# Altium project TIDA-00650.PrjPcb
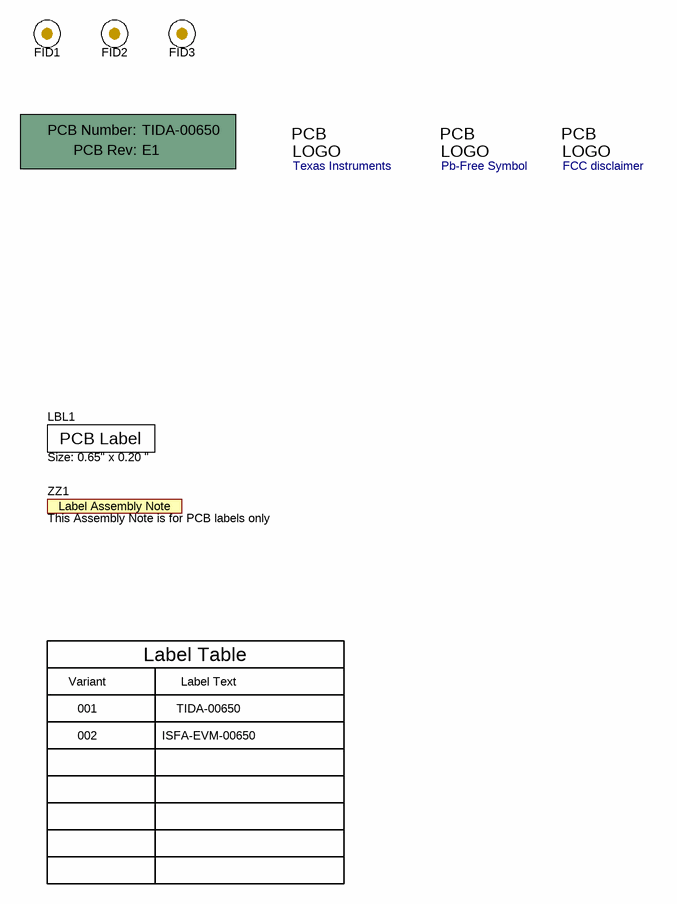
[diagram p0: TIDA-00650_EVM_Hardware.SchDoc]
CopyrightYear: 2015; PCB_Layout: AW; PCB_Rev: E1; PRJ_Customer: Public Release; PRJ_Engineer: AW; PRJ_Number: TIDA-00650; PRJ_Title: Wireless TC Sensor; SCH_Rev: E1; TechSupport: http://www.ti.com/support; TID: TIDA-00650
3 sheets, 54 parts. Net scope: flat (ports and power ports of the same name join across sheets).
Board file: TIDA-00650_EVM.PcbDoc
Sheets:
  TIDA-00650_CoverSheet.SchDoc
  TIDA-00650_EVM_Hardware.SchDoc
  TIDA-00650_ADC.SchDoc

## Sheet TIDA-00650_CoverSheet.SchDoc: Block Diagram
size 431 x 279 mm; Date: Not shown in title block; ApprovedBy: Not shown in title block; CheckedBy: Not shown in title block; Author: Not shown in title block; CompanyName: Not shown in title block; DrawnBy: AW; Engineer: Not shown in title block; Organization: Not shown in title block; Address1: Not shown in title block; Address2: Not shown in title block; Address3: Not shown in title block; Address4: Not shown in title block; DocumentNumber: 1; Revision: Use project parameter SCH_Rev; SheetNumber: 1; SheetTotal: 3; PageSetup: Record=PageOptions¦CenterHorizontal=True¦CenterVertical=True¦PrintScale=1.00¦XCorrection=1.00¦YCorrection=1.00¦PrintKind=0¦BorderSize=5000000¦LeftOffset=0¦BottomOffset=0¦Orientation=2¦PaperLength=1000¦PaperWidth=1000¦Scale=100¦PaperSource=15¦PrintQuality=600¦MediaType=1¦DitherType=10¦PaperKind=Letter¦PrintScaleMode=1

## Sheet TIDA-00650_EVM_Hardware.SchDoc: Hardware
size 431 x 279 mm; Date: Not shown in title block; ApprovedBy: Not shown in title block; CheckedBy: Not shown in title block; Author: Not shown in title block; CompanyName: Not shown in title block; DrawnBy: AW; Engineer: Not shown in title block; Organization: Not shown in title block; Address1: Not shown in title block; Address2: Not shown in title block; Address3: Not shown in title block; Address4: Not shown in title block; DocumentNumber: 1; Revision: Use project parameter SCH_Rev; SheetNumber: 3; SheetTotal: 3; PageSetup: Record=PageOptions¦CenterHorizontal=True¦CenterVertical=True¦PrintScale=1.00¦XCorrection=1.00¦YCorrection=1.00¦PrintKind=0¦BorderSize=5000000¦LeftOffset=0¦BottomOffset=0¦Orientation=2¦PaperLength=1000¦PaperWidth=1000¦Scale=100¦PaperSource=15¦PrintQuality=600¦MediaType=1¦DitherType=10¦PaperKind=Letter¦PrintScaleMode=1

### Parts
!PCB1  Printed Circuit Board  (value not drawn)  (mechanical)
FID1  Fiducial  [Fiducial10-20]  (value not drawn)
FID2  Fiducial  [Fiducial10-20]  (value not drawn)
FID3  Fiducial  [Fiducial10-20]  (value not drawn)
LBL1  Size: 0.65" x 0.20 "  [Label_650x200]
Logo1  Texas Instruments  [TI_Stacked_Overlay_Small]  (no BOM)
Logo2  Pb-Free Symbol  [Pb-Free_Overlay_Small]  (no BOM)
Logo3  FCC disclaimer  [FCC_disclaimer_stacked]  (no BOM)
ZZ1  This Assembly Note is for PCB labels only  [AssemblyNoteLabel]  (no BOM)

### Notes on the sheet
- Label Table
- Variant
- 001
- Label Text
- TIDA-00650
- 002
- ISFA-EVM-00650

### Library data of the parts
!PCB1 = PCB: Manufacturer: Any; PartNumber: TIDA-00650; SymbolCreator: a0412235
FID1-FID3 = Fiducial: Fiducial mark.  There is nothing to buy or mount.; SymbolCreator: codlsc
LBL1 = THT-14-423-10: Thermal Transfer Printable Labels, 0.650" W x 0.200" H - 10,000 per roll; Manufacturer: Brady; SymbolCreator: a0412235; CompType: Label
Logo1 = TI_Logo: Texas Instrument Corporate Signature; SymbolCreator: a0412235
Logo2 = Pb-Free: SymbolCreator: a0412235
Logo3 = FCC_disclaimer: SymbolCreator: codlsc
ZZ1 = AssemblyNoteLabel: SymbolCreator: a0412235

## Sheet TIDA-00650_ADC.SchDoc: Thermocouple ADC circuitry
size 431 x 279 mm; Date: Not shown in title block; ApprovedBy: Not shown in title block; CheckedBy: Not shown in title block; Author: Not shown in title block; CompanyName: Not shown in title block; DrawnBy: AW; Engineer: Not shown in title block; Organization: Not shown in title block; Address1: Not shown in title block; Address2: Not shown in title block; Address3: Not shown in title block; Address4: Not shown in title block; DocumentNumber: 1; Revision: Use project parameter SCH_Rev; SheetNumber: 2; SheetTotal: 3; PageSetup: Record=PageOptions¦CenterHorizontal=True¦CenterVertical=True¦PrintScale=1.00¦XCorrection=1.00¦YCorrection=1.00¦PrintKind=0¦BorderSize=5000000¦LeftOffset=0¦BottomOffset=0¦Orientation=2¦PaperLength=1000¦PaperWidth=1000¦Scale=100¦PaperSource=15¦PrintQuality=600¦MediaType=1¦DitherType=10¦PaperKind=Letter¦PrintScaleMode=1
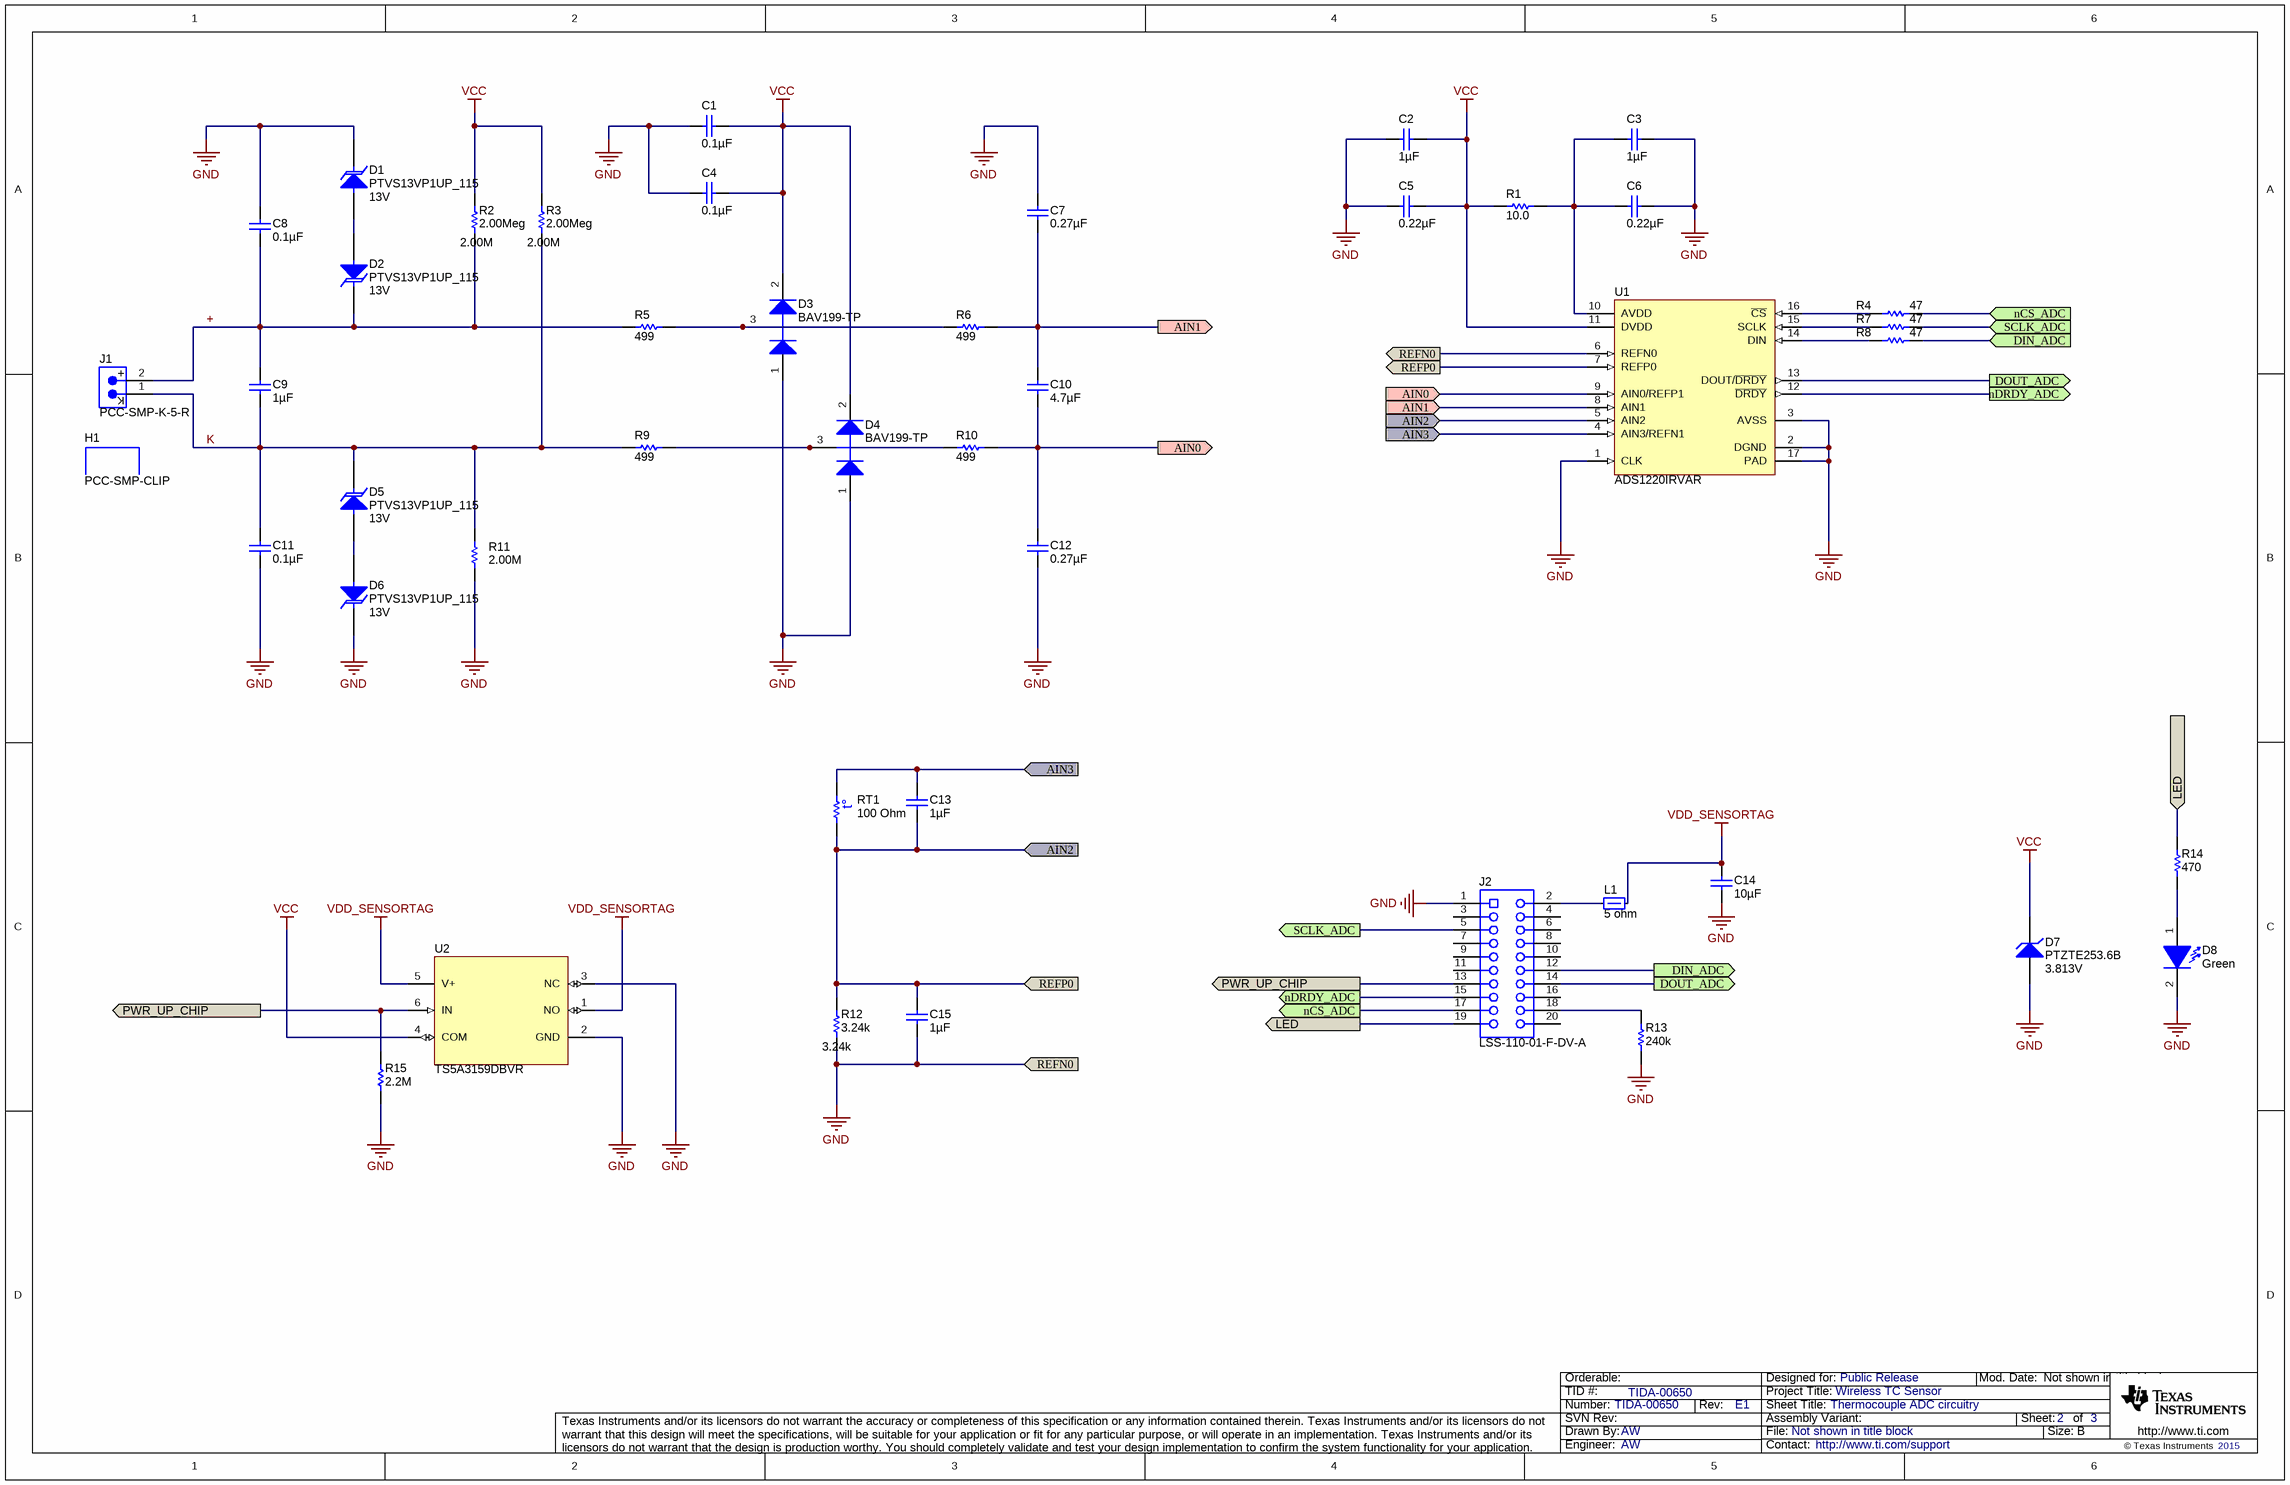
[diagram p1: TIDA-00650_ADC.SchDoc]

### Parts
C1  ValueDisplayed: 0.1µF  [0402]  (hidden comment: C1005X7R1H104K050BB)
C2  ValueDisplayed: 1µF  [0402S]  (hidden comment: GRM155R61A105KE15D)
C3  ValueDisplayed: 1µF  [0402S]  (hidden comment: GRM155R61A105KE15D)
C4  ValueDisplayed: 0.1µF  [0402]  (hidden comment: C1005X7R1H104K050BB)
C5  ValueDisplayed: 0.22µF  [0402S]  (hidden comment: GRM155R60J224KE01D)
C6  ValueDisplayed: 0.22µF  [0402S]  (hidden comment: GRM155R60J224KE01D)
C7  ValueDisplayed: 0.27µF  [0402L]  (hidden comment: GRM155R60J274KE01D)
C8  ValueDisplayed: 0.1µF  [0402]  (hidden comment: C1005X7R1H104K050BB)
C9  ValueDisplayed: 1µF  [0603]  (hidden comment: UMK107AB7105KA-T)
C10  ValueDisplayed: 4.7µF  [0402S]  (hidden comment: C1005X5R1A475K050BC)
C11  ValueDisplayed: 0.1µF  [0402]  (hidden comment: C1005X7R1H104K050BB)
C12  ValueDisplayed: 0.27µF  [0402L]  (hidden comment: GRM155R60J274KE01D)
C13  ValueDisplayed: 1µF  [0402S]  (hidden comment: GRM155R61A105KE15D)
C14  ValueDisplayed: 10µF  [0402S]  (hidden comment: GRM155R61A106ME11)
C15  ValueDisplayed: 1µF  [0402S]  (hidden comment: GRM155R61A105KE15D)
D1  PTVS13VP1UP_115  value 13V  [SOD-128]
D2  PTVS13VP1UP_115  value 13V  [SOD-128]
D3  BAV199-TP  [SOT-23]
D4  BAV199-TP  [SOT-23]
D5  PTVS13VP1UP_115  value 13V  [SOD-128]
D6  PTVS13VP1UP_115  value 13V  [SOD-128]
D7  PTZTE253.6B  value 3.813V  [SMA]
D8  value Green  [LG L29K_GREEN]  (hidden comment: LG L29K-G2J1-24-Z)
H1  PCC-SMP-CLIP  (mechanical)
J1  PCC-SMP-K-5-R  [Omega_PCC-SMP-K]
J2  LSS-110-01-F-DV-A  [Samtec_LSS-110-01-F-DV-A]
L1  value 5 ohm  [0603S]  (hidden comment: BLM18BB050SN1D)
R1  ValueDisplayed: 10.0  [0402S]  (hidden comment: CRCW040210R0FKED)
R2  value 2.00Meg  ValueDisplayed: 2.00M  [0402]  (hidden comment: CRCW04022M00FKED)
R3  value 2.00Meg  ValueDisplayed: 2.00M  [0402]  (hidden comment: CRCW04022M00FKED)
R4  ValueDisplayed: 47  [0402S]  (hidden comment: CRCW040247R0JNED)
R5  ValueDisplayed: 499  [0402]  (hidden comment: CRCW0402499RFKED)
R6  ValueDisplayed: 499  [0402L]  (hidden comment: CRCW0402499RFKED)
R7  ValueDisplayed: 47  [0402S]  (hidden comment: CRCW040247R0JNED)
R8  ValueDisplayed: 47  [0402S]  (hidden comment: CRCW040247R0JNED)
R9  ValueDisplayed: 499  [0402]  (hidden comment: CRCW0402499RFKED)
R10  ValueDisplayed: 499  [0402L]  (hidden comment: CRCW0402499RFKED)
R11  ValueDisplayed: 2.00M  [0402]  (hidden comment: CRCW04022M00FKED)
R12  value 3.24k  [1206L]  (hidden comment: PFC-W1206R-12-3241-B)
R13  ValueDisplayed: 240k  [0402]  (hidden comment: CRCW0402240KFKED)
R14  ValueDisplayed: 470  [0402]  (hidden comment: ERJ-2RKF4700X)
R15  ValueDisplayed: 2.2M  [0402S]  (hidden comment: CRCW04022M20JNED)
RT1  value 100 Ohm  [TO-92_Heraeus]  (hidden comment: 32209210)
U1  ADS1220IRVAR  [RVA0016A]
U2  TS5A3159DBVR  [DBV0006A_N]

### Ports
AIN0 (in), AIN0 (out), AIN1 (in), AIN1 (out), AIN2, AIN2 (in), AIN3, AIN3 (in), DIN_ADC (in), DIN_ADC (out), DOUT_ADC (out), LED, nCS_ADC (in), nCS_ADC (out), nDRDY_ADC (out), PWR_UP_CHIP, REFN0, REFP0, SCLK_ADC (in), SCLK_ADC (out)

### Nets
GND: C1.1 C2.1 C3.2 C4.1 C5.1 C6.2 C7.1 C8.1 C11.2 C12.2 C14.2 C15.2 D1.1(K) D3.1(A) D4.1(A) D6.1(K) D7.2(A) D8.2(K) J2.1 R11.1 R12.1 R13.1 R15.1 U1.1(CLK) U1.2(DGND) U1.3(AVSS) U1.6(REFN0) U1.17(PAD) U2.2(GND) U2.3(NC) ; port REFN0
VCC: C1.2 C2.2 C4.2 C5.2 D3.2(K) D4.2(K) D7.1(K) R1.2 R2.2 R3.2 U1.11(DVDD) U2.4(COM)
VDD_SENSORTAG: C14.1 L1.2 U2.1(NO) U2.5(V+)
+: C8.2 C9.1 D2.1(K) J1.2 R2.1 R5.1
AIN0: C10.2 C12.1 R10.2 U1.9(AIN0/REFP1) ; port AIN0
AIN1: C7.2 C10.1 R6.2 U1.8(AIN1) ; port AIN1
AIN2: C13.2 C15.1 R12.2 RT1.1 U1.5(AIN2) U1.7(REFP0) ; port REFP0, port AIN2
AIN3: C13.1 RT1.2 U1.4(AIN3/REFN1) ; port AIN3
DIN_ADC: J2.12 R8.2 ; port DIN_ADC
DOUT_ADC: J2.14 U1.13(DOUT/~{DRDY}) ; port DOUT_ADC
K: C9.2 C11.1 D5.1(K) J1.1 R3.1 R9.1 R11.2
LED: J2.19 R14.2 ; port LED
nCS_ADC: J2.17 R4.2 ; port nCS_ADC
nDRDY_ADC: J2.15 U1.12(~{DRDY}) ; port nDRDY_ADC
PWR_UP_CHIP: J2.13 R15.2 U2.6(IN) ; port PWR_UP_CHIP
SCLK_ADC: J2.5 R7.2 ; port SCLK_ADC
NetC3_1: C3.1 C6.1 R1.1 U1.10(AVDD)
NetD1_2: D1.2(A) D2.2(A)
NetD3_3: D3.3(C) R5.2 R6.1
NetD4_3: D4.3(C) R9.2 R10.1
NetD5_2: D5.2(A) D6.2(A)
NetD8_1: D8.1(A) R14.1
NetJ2_2: J2.2 L1.1
NetJ2_18: J2.18 R13.2
NetR4_1: R4.1 U1.16(~{CS})
NetR7_1: R7.1 U1.15(SCLK)
NetR8_1: R8.1 U1.14(DIN)

Not connected (* = marked no-connect by the designer): J2 3 4 6 7 8 9 10 11 16 20

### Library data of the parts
C1 C4 C8 C11 = C1005X7R1H104K050BB: CAP, CERM, 0.1 µF, 50 V, +/- 10%, X7R, 0402; Manufacturer: TDK; Polarized: N; CompType: Capacitor; Value: 0.1uF; U/M: EA; Cap_F: 0.0000001; Tolerance_%: 10; Value1: Unknown; VDC_V: 50; Value2: 50V; TaMin_C: -55; TaMax_C: 125
C2 C3 C13 C15 = GRM155R61A105KE15D: CAP, CERM, 1 µF, 10 V, +/- 10%, X5R, 0402; Manufacturer: MuRata; Polarized: N; CompType: Capacitor; Value: 1uF; U/M: EA; Cap_F: 0.000001; Tolerance_%: 10; Value1: Unknown; Value2: 10V; TaMin_C: -55; TaMax_C: 85; Cap_Case: 0402
C5 C6 = GRM155R60J224KE01D: CAP, CERM, 0.22 µF, 6.3 V, +/- 10%, X5R, 0402; Manufacturer: MuRata; Polarized: N; CompType: Capacitor; Value: 0.22uF; U/M: EA; Cap_F: 0.00000022; Tolerance_%: 10; Value1: Unknown; VDC_V: 6.3; Value2: 6.3V; TaMin_C: -55; TaMax_C: 85; Cap_Case: 0402
C7 C12 = GRM155R60J274KE01D: CAP, CERM, 0.27 µF, 6.3 V, +/- 10%, X5R, 0402; Manufacturer: MuRata; Polarized: N; CompType: Capacitor; Value: 0.27uF; U/M: EA; Cap_F: 0.00000027; Tolerance_%: 10; Value1: Unknown; VDC_V: 6.3; Value2: 6.3V; TaMin_C: -55; TaMax_C: 85; Cap_Case: 0402
C9 = UMK107AB7105KA-T: CAP, CERM, 1 µF, 50 V, +/- 10%, X7R, 0603; Manufacturer: Taiyo Yuden; Polarized: N; CompType: Capacitor; Value: 1uF; U/M: EA; Cap_F: 0.000001; Tolerance_%: 10; Value1: Unknown; VDC_V: 50; Value2: 50V; TaMin_C: -55; TaMax_C: 125
C10 = C1005X5R1A475K050BC: CAP, CERM, 4.7 µF, 10 V, +/- 10%, X5R, 0402; Manufacturer: TDK; Polarized: N; CompType: Capacitor; Value: 4.7uF; U/M: EA; Cap_F: 0.0000047; Tolerance_%: 10; Value1: Unknown; Value2: 10V; TaMin_C: -55; TaMax_C: 85; Cap_Case: 0402
C14 = GRM155R61A106ME11: CAP, CERM, 10 µF, 10 V, +/- 20%, X5R, 0402; Manufacturer: MuRata; Polarized: N; CompType: Capacitor; Value: 10uF; U/M: EA; Cap_F: 0.00001; Tolerance_%: 20; Value1: Unknown; VDC_V: 10; Value2: 10V; TaMin_C: -55; TaMax_C: 85; Cap_Case: 0402
D1 D2 D5 D6 = PTVS13VP1UP_115: Diode, TVS, Uni, 13 V, 600 W, SOD-128; Manufacturer: NXP Semiconductor; U/M: EA; Power_W: 600; Vr_V: 13; Value1: 600W
D3 D4 = BAV199-TP: Diode, Switching, 70 V, 0.215 A, SOT-23; Manufacturer: Micro Commercial Components; U/M: EA; Value: 70V; Value1: 0.215A; Io_A: 0.215; Vr_V: 70; TJmax_C: 150
D7 = PTZTE253.6B: Diode, Zener, 3.813 V, 1 W, SMA; Manufacturer: Rohm; SymbolCreator: a0412235; U/M: EA; Power_W: 1; Vz_V: 3.813; Value1: 1W
D8 = LG L29K-G2J1-24-Z: LED, Green, SMD; Manufacturer: OSRAM; Vf_V: 1.7; Value2: 1.7V; Io_A: 0.002; Tjmax_C: 110; Value1: W; U/M: EA
H1 = PCC-SMP-CLIP: Mounting bracket for PCC-SMP; Manufacturer: Omega; SymbolCreator: Altium; CompType: Hardware
J1 = PCC-SMP-K-5-R: Circuit Board Thermocouple Connector, Miniature Size, Type K, Horizontal installation, TH; Manufacturer: Omega; SymbolCreator: a0799628; U/M: EA
J2 = LSS-110-01-F-DV-A: Terminal/Socket Combo, 25mil, 10x2, Gold, SMT; Manufacturer: Samtec; SymbolCreator: a0412235; CompType: Connector; U/M: EA
L1 = BLM18BB050SN1D: Ferrite Bead, 5 ohm @ 100 MHz, 0.7 A, 0603; Manufacturer: MuRata; Imax_A: 0.7; DCR_ohm: 0.05; Value1: 0.05 ohm; Value2: 0.7A; ZTyp@100MHz_Ohm: 5
R1 = CRCW040210R0FKED: RES, 10.0, 1%, 0.063 W, 0402; Manufacturer: Vishay-Dale; CompType: Resistor; Value: 10.0; Res_ohm: 10; Value_Code: 10R0; Tolerance_%: 1; Power_W: 0.063; Value2: 0.063W; VDC_V: 50; TempCo: 100 ppm/C; EIA_Code: E96; U/M: EA
R2 R3 = CRCW04022M00FKED: RES, 2.00 M, 1%, 0.063 W, 0402; Manufacturer: Vishay-Dale; CompType: Resistor; Res_ohm: 2000000; Value_Code: 2M00; Tolerance_%: 1; Power_W: 0.063; Value2: 0.063W; VDC_V: 50; TempCo: 100 ppm/C; EIA_Code: E96; U/M: EA
R4 R7 R8 = CRCW040247R0JNED: RES, 47, 5%, 0.063 W, 0402; Manufacturer: Vishay-Dale; CompType: Resistor; Value: 47; Value_Code: 47R0; Tolerance_%: 5; Power_W: 0.063; Value2: 0.063W; VDC_V: 50; TempCo: 200 ppm/C; EIA_Code: E24; U/M: EA
R5 R6 R9 R10 = CRCW0402499RFKED: RES, 499, 1%, 0.063 W, 0402; Manufacturer: Vishay-Dale; CompType: Resistor; Value: 499; Value_Code: 499R; Tolerance_%: 1; Power_W: 0.063; Value2: 0.063W; VDC_V: 50; TempCo: 100 ppm/C; EIA_Code: E96; U/M: EA
R11 = CRCW04022M00FKED: RES, 2.00 M, 1%, 0.063 W, 0402; Manufacturer: Vishay-Dale; CompType: Resistor; Value: 2.00Meg; Res_ohm: 2000000; Value_Code: 2M00; Tolerance_%: 1; Power_W: 0.063; Value2: 0.063W; VDC_V: 50; TempCo: 100 ppm/C; EIA_Code: E96; U/M: EA
R12 = PFC-W1206R-12-3241-B: RES, 3.24 k, 0.1%, 0.333 W, 1206; Manufacturer: TT Electronics/IRC; CompType: Resistor; Res_ohm: 3240; Value_Code: 3k24; Tolerance_%: 0.1; Power_W: 0.333; Value2: 0.333W; TempCo: 10 ppm/C; EIA_Code: E192; U/M: EA
R13 = CRCW0402240KFKED: RES, 240 k, 1%, 0.063 W, 0402; Manufacturer: Vishay-Dale; CompType: Resistor; Value: 240k; Res_ohm: 240000; Tolerance_%: 1; Power_W: 0.063; Value2: 0.063W; VDC_V: 50; TempCo: 100 ppm/C; U/M: EA
R14 = ERJ-2RKF4700X: RES, 470, 1%, 0.1 W, 0402; Manufacturer: Panasonic; CompType: Resistor; Value: 470; Value_Code: 470R; Tolerance_%: 1; Power_W: 0.1; Value2: 0.1W; VDC_V: 50; TempCo: 100 ppm/C; U/M: EA
R15 = CRCW04022M20JNED: RES, 2.2 M, 5%, 0.063 W, 0402; Manufacturer: Vishay-Dale; CompType: Resistor; Value: 2.2Meg; Res_ohm: 2200000; Value_Code: 2M20; Tolerance_%: 5; Power_W: 0.063; Value2: 0.063W; VDC_V: 50; TempCo: 200 ppm/C; EIA_Code: E24; U/M: EA
RT1 = 32209210: Temperature Sensor, 100ohm, TC=+3850ppm, TO-92, TH; Manufacturer: Heraeus Sensor Technology; CompType: Temp Sensor
U1 = ADS1220IRVAR: Low-Power, Low-Noise, 24-Bit Analog-to-Digital Converter for Small Signal Sensors, RVA0016A; Alternate PartNumber: ADS1220IRVAT; Manufacturer: Texas Instruments; SymbolCreator: x0208326; CompType: IC; U/M: EA
U2 = TS5A3159DBVR: 1-Ω SPDT Analog Switch, DBV0006A; Alternate PartNumber: TS5A3159DBVT; Manufacturer: Texas Instruments; SymbolCreator: a0799628; CompType: IC; U/M: EA

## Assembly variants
001: not fitted D7 FID1 FID2 FID3 LBL1 R3
002: not fitted D7 FID1 FID2 FID3 R3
